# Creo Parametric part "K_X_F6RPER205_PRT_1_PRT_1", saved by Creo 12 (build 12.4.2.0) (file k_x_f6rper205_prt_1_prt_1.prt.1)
Units: Custom; MM, KILOGRAM, SECS

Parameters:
  PTC_WM_ITERATION = "0"
  PTC_WM_VERSION = "-.0"
  PTC_WM_LIFECYCLE_STATE = "In Work"
  PTC_WM_LIFECYCLE = "MO_CADDocument"
  PTC_WM_CREATED_BY = "Maximilian Roepper (Z0017RMS: MO)"
  PTC_WM_CREATED_ON = "18-Sep-26 11:36:42 AM"
  PTC_WM_MODIFIED_BY = "Maximilian Roepper (Z0017RMS: MO)"
  PTC_WM_MODIFIED_ON = "18-Sep-26 11:36:46 AM"
  PDMLINKNUMBER = "PDM000071454830"
  PTC_WM_NAME = "k_x_f6rper205_prt_1_prt_1.prt"
  PTC_WM_NUMBER = "PDM000071454830"

Other parameters: WEIGHT, WEIGHT_FACTOR, WEIGHT_ADD, _MASS_TEMP, _DIFF_TEMP, MC_ERRORS, SUPPLIER

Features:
  1. coordinate system
  2. datum plane "PRT_YZ"
  3. datum plane "PRT_XY"
  4. datum plane "PRT_XZ"
  5. coordinate system
  6. datum axis
  7. datum axis
  8. datum axis
  9. coordinate system
  10. imported feature
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
Other named items: PRT, SIEMENS_MO, DRW_VIEW_ORG, PRT_X, PRT_Y, PRT_Z, CS0, ROUGH_GROB

Layers: 00_STD_CSYS-KSYS, 01_STD_PLANES-EBENEN, 02_STD_AXES-ACHSEN, 03_STD_CSYS-KSYS, 24_IMPORT_FEAT-IMPORT_KE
